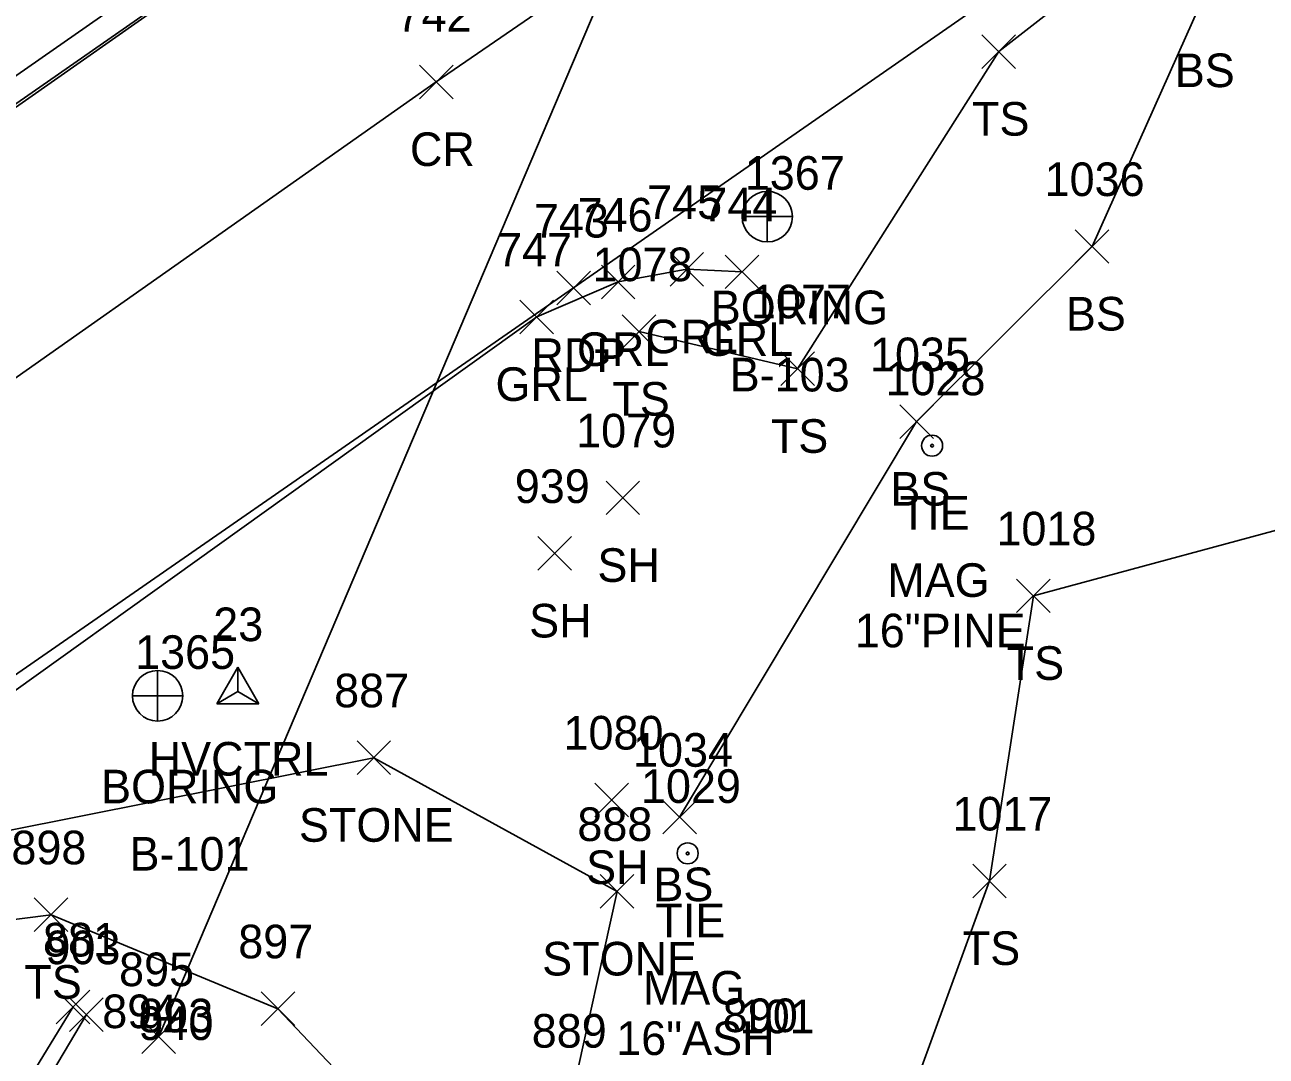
# Model space of a CAD drawing. Extents: x 1528286 to 1556263, y 492387 to 508952.
# Drawn here: x 1528636.2 to 1528710.1, y 492732.7 to 492794 of the extents above; entities that cross this region are included whole.
import ezdxf

# ---------------------------------------------------------------- set-up
doc = ezdxf.new("R2010")
doc.units = 0
for name, color, linetype in [('C_A', 7, 'Continuous'), ('C_C', 7, 'Continuous'), ('C_I', 7, 'Continuous'), ('CBP', 7, 'Continuous'), ('CPSM', 7, 'Continuous'), ('D_I', 7, 'Continuous'), ('D_TIC', 7, 'Continuous'), ('DCP', 7, 'Continuous'), ('G_A', 7, 'Continuous'), ('G_C', 7, 'Continuous'), ('G_I', 7, 'Continuous'), ('GA_P', 7, 'Continuous'), ('L_A', 7, 'Continuous'), ('L_I', 7, 'Continuous'), ('L_TIC', 7, 'Continuous'), ('LASF', 7, 'Continuous'), ('LAWE', 7, 'Continuous'), ('LELB', 7, 'Continuous'), ('M_I', 7, 'Continuous'), ('P_A', 7, 'Continuous'), ('P_I', 7, 'Continuous'), ('P_TIC', 7, 'Continuous'), ('PET', 7, 'Continuous'), ('PRC', 7, 'Continuous'), ('R_A', 7, 'Continuous'), ('R_I', 7, 'Continuous'), ('R_TIC', 7, 'Continuous'), ('RGR', 7, 'Continuous')]:
    doc.layers.add(name, color=color, linetype=linetype)

msp = doc.modelspace()

# ---------------------------------------------------------------- linework, layer by layer
at = {"layer": 'CBP'}
for centre, radius in [((1528690.22, 492769.002), 0.625), ((1528690.22, 492769.002), 0.625), ((1528690.22, 492769.002), 0.0833), ((1528690.22, 492769.002), 0.0833), ((1528675.675, 492744.745), 0.625), ((1528675.675, 492744.745), 0.625), ((1528675.675, 492744.745), 0.0833), ((1528675.675, 492744.745), 0.0833)]:
    msp.add_circle(centre, radius, dxfattribs=at)
at = {"layer": 'CPSM'}
for p, q in [((1528647.655, 492753.65), (1528648.905, 492755.815)), ((1528647.655, 492753.65), (1528648.905, 492755.815)), ((1528650.155, 492753.65), (1528648.905, 492755.815)), ((1528648.905, 492754.371), (1528648.905, 492755.815)), ((1528650.155, 492753.65), (1528648.905, 492755.815)), ((1528648.905, 492754.371), (1528648.905, 492755.815)), ((1528647.655, 492753.65), (1528648.905, 492754.371)), ((1528647.655, 492753.65), (1528648.905, 492754.371)), ((1528648.905, 492754.371), (1528648.905, 492754.371)), ((1528648.905, 492754.371), (1528650.155, 492753.65)), ((1528648.905, 492754.371), (1528648.905, 492754.371)), ((1528648.905, 492754.371), (1528650.155, 492753.65)), ((1528647.655, 492753.65), (1528650.155, 492753.65)), ((1528647.655, 492753.65), (1528650.155, 492753.65))]:
    msp.add_line(p, q, dxfattribs=at)
at = {"layer": 'D_TIC'}
for points in [[(1528643.198, 492732.843), (1528645.198, 492734.843)], [(1528645.198, 492732.843), (1528643.198, 492734.843)], [(1528643.198, 492732.843), (1528645.198, 492734.843)], [(1528645.198, 492732.843), (1528643.198, 492734.843)]]:
    msp.add_lwpolyline(points, dxfattribs=at)
at = {"layer": 'DCP'}
msp.add_lwpolyline([(1528644.198, 492733.843), (1528697.661, 492859.59)], dxfattribs=at)
msp.add_lwpolyline([(1528644.198, 492733.843), (1528697.661, 492859.59)], dxfattribs=at)
at = {"layer": 'GA_P'}
for p, q in [((1528680.416, 492782.628), (1528680.416, 492784.128)), ((1528680.416, 492782.628), (1528680.416, 492784.128)), ((1528680.416, 492782.628), (1528678.916, 492782.628)), ((1528680.416, 492782.628), (1528678.916, 492782.628)), ((1528681.916, 492782.628), (1528680.416, 492782.628)), ((1528680.416, 492781.128), (1528680.416, 492782.628)), ((1528681.916, 492782.628), (1528680.416, 492782.628)), ((1528680.416, 492781.128), (1528680.416, 492782.628)), ((1528644.13, 492754.118), (1528644.13, 492755.618)), ((1528644.13, 492754.118), (1528644.13, 492755.618)), ((1528644.13, 492754.118), (1528642.63, 492754.118)), ((1528644.13, 492754.118), (1528642.63, 492754.118)), ((1528645.63, 492754.118), (1528644.13, 492754.118)), ((1528644.13, 492752.618), (1528644.13, 492754.118)), ((1528645.63, 492754.118), (1528644.13, 492754.118)), ((1528644.13, 492752.618), (1528644.13, 492754.118))]:
    msp.add_line(p, q, dxfattribs=at)
for centre, start, end in [((1528680.415, 492782.628), 90, 180), ((1528680.415, 492782.628), 90, 180), ((1528680.415, 492782.628), 0, 90), ((1528680.415, 492782.628), 0, 90), ((1528680.415, 492782.628), 180, 270), ((1528680.415, 492782.628), 180, 270), ((1528680.415, 492782.628), 270, 0), ((1528680.415, 492782.628), 270, 0), ((1528644.13, 492754.118), 90, 180), ((1528644.13, 492754.118), 90, 180), ((1528644.13, 492754.118), 0, 90), ((1528644.13, 492754.118), 0, 90), ((1528644.13, 492754.118), 180, 270), ((1528644.13, 492754.118), 180, 270), ((1528644.13, 492754.118), 270, 0), ((1528644.13, 492754.118), 270, 0)]:
    msp.add_arc(centre, 1.5, start, end, dxfattribs=at)
at = {"layer": 'L_TIC'}
for points in [[(1528693.188, 492791.448), (1528695.188, 492793.448)], [(1528695.188, 492791.448), (1528693.188, 492793.448)], [(1528693.188, 492791.448), (1528695.188, 492793.448)], [(1528695.188, 492791.448), (1528693.188, 492793.448)], [(1528698.745, 492779.853), (1528700.745, 492781.853)], [(1528700.745, 492779.853), (1528698.745, 492781.853)], [(1528698.745, 492779.853), (1528700.745, 492781.853)], [(1528700.745, 492779.853), (1528698.745, 492781.853)], [(1528671.784, 492774.788), (1528673.784, 492776.788)], [(1528673.784, 492774.788), (1528671.784, 492776.788)], [(1528671.784, 492774.788), (1528673.784, 492776.788)], [(1528673.784, 492774.788), (1528671.784, 492776.788)], [(1528681.217, 492772.575), (1528683.217, 492774.575)], [(1528683.217, 492772.575), (1528681.217, 492774.575)], [(1528681.217, 492772.575), (1528683.217, 492774.575)], [(1528683.217, 492772.575), (1528681.217, 492774.575)], [(1528688.3, 492769.432), (1528690.3, 492771.432)], [(1528690.3, 492769.432), (1528688.3, 492771.432)], [(1528688.3, 492769.432), (1528690.3, 492771.432)], [(1528690.3, 492769.432), (1528688.3, 492771.432)], [(1528670.817, 492764.897), (1528672.817, 492766.897)], [(1528672.817, 492764.897), (1528670.817, 492766.897)], [(1528670.817, 492764.897), (1528672.817, 492766.897)], [(1528672.817, 492764.897), (1528670.817, 492766.897)], [(1528666.755, 492761.589), (1528668.755, 492763.589)], [(1528668.755, 492761.589), (1528666.755, 492763.589)], [(1528666.755, 492761.589), (1528668.755, 492763.589)], [(1528668.755, 492761.589), (1528666.755, 492763.589)], [(1528695.254, 492759.067), (1528697.254, 492761.067)], [(1528697.254, 492759.067), (1528695.254, 492761.067)], [(1528695.254, 492759.067), (1528697.254, 492761.067)], [(1528697.254, 492759.067), (1528695.254, 492761.067)], [(1528655.998, 492749.434), (1528657.998, 492751.434)], [(1528657.998, 492749.434), (1528655.998, 492751.434)], [(1528655.998, 492749.434), (1528657.998, 492751.434)], [(1528657.998, 492749.434), (1528655.998, 492751.434)], [(1528670.145, 492746.922), (1528672.145, 492748.922)], [(1528672.145, 492746.922), (1528670.145, 492748.922)], [(1528670.145, 492746.922), (1528672.145, 492748.922)], [(1528672.145, 492746.922), (1528670.145, 492748.922)], [(1528674.196, 492745.898), (1528676.196, 492747.898)], [(1528676.196, 492745.898), (1528674.196, 492747.898)], [(1528674.196, 492745.898), (1528676.196, 492747.898)], [(1528676.196, 492745.898), (1528674.196, 492747.898)], [(1528692.638, 492742.104), (1528694.638, 492744.104)], [(1528694.638, 492742.104), (1528692.638, 492744.104)], [(1528692.638, 492742.104), (1528694.638, 492744.104)], [(1528694.638, 492742.104), (1528692.638, 492744.104)], [(1528670.474, 492741.478), (1528672.474, 492743.478)], [(1528672.474, 492741.478), (1528670.474, 492743.478)], [(1528670.474, 492741.478), (1528672.474, 492743.478)], [(1528672.474, 492741.478), (1528670.474, 492743.478)], [(1528636.79, 492740.092), (1528638.79, 492742.092)], [(1528638.79, 492740.092), (1528636.79, 492742.092)], [(1528636.79, 492740.092), (1528638.79, 492742.092)], [(1528638.79, 492740.092), (1528636.79, 492742.092)], [(1528638.098, 492734.608), (1528640.098, 492736.608)], [(1528640.098, 492734.608), (1528638.098, 492736.608)], [(1528638.098, 492734.608), (1528640.098, 492736.608)], [(1528640.098, 492734.608), (1528638.098, 492736.608)], [(1528650.291, 492734.499), (1528652.291, 492736.499)], [(1528652.291, 492734.499), (1528650.291, 492736.499)], [(1528650.291, 492734.499), (1528652.291, 492736.499)], [(1528652.291, 492734.499), (1528650.291, 492736.499)], [(1528638.893, 492734.148), (1528640.893, 492736.148)], [(1528640.893, 492734.148), (1528638.893, 492736.148)], [(1528638.893, 492734.148), (1528640.893, 492736.148)], [(1528640.893, 492734.148), (1528638.893, 492736.148)]]:
    msp.add_lwpolyline(points, dxfattribs=at)
at = {"layer": 'LASF'}
msp.add_lwpolyline([(1528639.098, 492735.608), (1528627.241, 492716.245), (1528613.209, 492719.227), (1528607.642, 492721.098), (1528613.116, 492733.507), (1528630.781, 492745.216), (1528656.998, 492750.434), (1528671.474, 492742.478), (1528668.765, 492730.184), (1528658.721, 492713.827), (1528653.721, 492719.292), (1528645.341, 492731.093)], dxfattribs=at)
msp.add_lwpolyline([(1528639.098, 492735.608), (1528627.241, 492716.245), (1528613.209, 492719.227), (1528607.642, 492721.098), (1528613.116, 492733.507), (1528630.781, 492745.216), (1528656.998, 492750.434), (1528671.474, 492742.478), (1528668.765, 492730.184), (1528658.721, 492713.827), (1528653.721, 492719.292), (1528645.341, 492731.093)], dxfattribs=at)
at = {"layer": 'LAWE'}
msp.add_lwpolyline([(1528639.893, 492735.148), (1528628.638, 492716.197), (1528619.322, 492697.772), (1528600.014, 492685.78), (1528586.494, 492675.208), (1528555.765, 492651.711), (1528552.059, 492644.142), (1528537.626, 492632.534), (1528523.345, 492621.851), (1528510.87, 492609.533), (1528497.291, 492599.489), (1528482.777, 492583.151), (1528460.774, 492562.048), (1528436.992, 492551.704), (1528418.951, 492545.204), (1528399.482, 492529.93), (1528387.952, 492519.312), (1528358.196, 492480.955)], dxfattribs=at)
msp.add_lwpolyline([(1528639.893, 492735.148), (1528628.638, 492716.197), (1528619.322, 492697.772), (1528600.014, 492685.78), (1528586.494, 492675.208), (1528555.765, 492651.711), (1528552.059, 492644.142), (1528537.626, 492632.534), (1528523.345, 492621.851), (1528510.87, 492609.533), (1528497.291, 492599.489), (1528482.777, 492583.151), (1528460.774, 492562.048), (1528436.992, 492551.704), (1528418.951, 492545.204), (1528399.482, 492529.93), (1528387.952, 492519.312), (1528358.196, 492480.955)], dxfattribs=at)
at = {"layer": 'LELB'}
for points in [[(1528511.531, 492702.846), (1528534.14, 492721.314), (1528572.642, 492751.164), (1528586.729, 492763.586), (1528600.497, 492766.346), (1528613.458, 492775.516), (1528652.2, 492802.526), (1528688.619, 492828.262), (1528710.289, 492843.118), (1528742.907, 492866.471), (1528778.713, 492891.266), (1528817.445, 492919.082), (1528857.746, 492946.937), (1528897.372, 492973.983), (1528940.286, 493003.739)], [(1528511.531, 492702.846), (1528534.14, 492721.314), (1528572.642, 492751.164), (1528586.729, 492763.586), (1528600.497, 492766.346), (1528613.458, 492775.516), (1528652.2, 492802.526), (1528688.619, 492828.262), (1528710.289, 492843.118), (1528742.907, 492866.471), (1528778.713, 492891.266), (1528817.445, 492919.082), (1528857.746, 492946.937), (1528897.372, 492973.983), (1528940.286, 493003.739)], [(1528946.969, 492932.586), (1528919.959, 492926.163), (1528896.398, 492920.638), (1528892.931, 492919.077), (1528869.957, 492910.976), (1528843.058, 492896.384), (1528834.233, 492890.275), (1528806.992, 492871.856), (1528782.492, 492854.983), (1528750.989, 492833.046), (1528710.78, 492805.361), (1528694.188, 492792.448), (1528682.217, 492773.575), (1528672.784, 492775.788)], [(1528946.969, 492932.586), (1528919.959, 492926.163), (1528896.398, 492920.638), (1528892.931, 492919.077), (1528869.957, 492910.976), (1528843.058, 492896.384), (1528834.233, 492890.275), (1528806.992, 492871.856), (1528782.492, 492854.983), (1528750.989, 492833.046), (1528710.78, 492805.361), (1528694.188, 492792.448), (1528682.217, 492773.575), (1528672.784, 492775.788)], [(1528675.196, 492746.898), (1528689.3, 492770.432), (1528699.745, 492780.853), (1528706.225, 492795.334), (1528738.423, 492819.149), (1528757.61, 492832.596), (1528783.379, 492849.877), (1528832.015, 492885.927)], [(1528675.196, 492746.898), (1528689.3, 492770.432), (1528699.745, 492780.853), (1528706.225, 492795.334), (1528738.423, 492819.149), (1528757.61, 492832.596), (1528783.379, 492849.877), (1528832.015, 492885.927)], [(1528705.259, 492704.943), (1528686.116, 492722.486), (1528693.638, 492743.104), (1528696.254, 492760.067), (1528714.163, 492764.9), (1528717.514, 492785.825)], [(1528705.259, 492704.943), (1528686.116, 492722.486), (1528693.638, 492743.104), (1528696.254, 492760.067), (1528714.163, 492764.9), (1528717.514, 492785.825)], [(1528661.587, 492724.641), (1528651.291, 492735.499), (1528637.79, 492741.092), (1528626.005, 492739.602), (1528615.037, 492725.446), (1528613.03, 492719.826)], [(1528661.587, 492724.641), (1528651.291, 492735.499), (1528637.79, 492741.092), (1528626.005, 492739.602), (1528615.037, 492725.446), (1528613.03, 492719.826)]]:
    msp.add_lwpolyline(points, dxfattribs=at)
at = {"layer": 'P_TIC'}
for points in [[(1528659.714, 492789.64), (1528661.714, 492791.64)], [(1528661.714, 492789.64), (1528659.714, 492791.64)], [(1528659.714, 492789.64), (1528661.714, 492791.64)], [(1528661.714, 492789.64), (1528659.714, 492791.64)], [(1528667.887, 492777.385), (1528669.887, 492779.385)], [(1528669.887, 492777.385), (1528667.887, 492779.385)], [(1528667.887, 492777.385), (1528669.887, 492779.385)], [(1528669.887, 492777.385), (1528667.887, 492779.385)]]:
    msp.add_lwpolyline(points, dxfattribs=at)
at = {"layer": 'PET'}
for points in [[(1528796.008, 492866.532), (1528760.738, 492842.185), (1528727.561, 492819.312), (1528705.978, 492804.168), (1528668.887, 492778.385)], [(1528796.008, 492866.532), (1528760.738, 492842.185), (1528727.561, 492819.312), (1528705.978, 492804.168), (1528668.887, 492778.385)], [(1528653.332, 492801.515), (1528614.2, 492774.085)], [(1528653.332, 492801.515), (1528614.2, 492774.085)], [(1528668.887, 492778.385), (1528630.871, 492752.063)], [(1528668.887, 492778.385), (1528630.871, 492752.063)]]:
    msp.add_lwpolyline(points, dxfattribs=at)
at = {"layer": 'PRC'}
for points in [[(1528788.693, 492878.598), (1528752.937, 492854.076), (1528719.055, 492830.747), (1528697.879, 492816.158), (1528660.714, 492790.64)], [(1528788.693, 492878.598), (1528752.937, 492854.076), (1528719.055, 492830.747), (1528697.879, 492816.158), (1528660.714, 492790.64)], [(1528660.714, 492790.64), (1528622.148, 492763.521)], [(1528660.714, 492790.64), (1528622.148, 492763.521)]]:
    msp.add_lwpolyline(points, dxfattribs=at)
at = {"layer": 'R_TIC'}
for points in [[(1528674.624, 492778.498), (1528676.624, 492780.498)], [(1528676.624, 492778.498), (1528674.624, 492780.498)], [(1528674.624, 492778.498), (1528676.624, 492780.498)], [(1528676.624, 492778.498), (1528674.624, 492780.498)], [(1528677.913, 492778.345), (1528679.913, 492780.345)], [(1528679.913, 492778.345), (1528677.913, 492780.345)], [(1528677.913, 492778.345), (1528679.913, 492780.345)], [(1528679.913, 492778.345), (1528677.913, 492780.345)], [(1528670.539, 492777.742), (1528672.539, 492779.742)], [(1528672.539, 492777.742), (1528670.539, 492779.742)], [(1528670.539, 492777.742), (1528672.539, 492779.742)], [(1528672.539, 492777.742), (1528670.539, 492779.742)], [(1528665.696, 492775.663), (1528667.696, 492777.663)], [(1528667.696, 492775.663), (1528665.696, 492777.663)], [(1528665.696, 492775.663), (1528667.696, 492777.663)], [(1528667.696, 492775.663), (1528665.696, 492777.663)]]:
    msp.add_lwpolyline(points, dxfattribs=at)
at = {"layer": 'RGR'}
for points in [[(1528653.301, 492801.623), (1528614.133, 492774.352)], [(1528653.301, 492801.623), (1528614.133, 492774.352)], [(1528678.913, 492779.345), (1528675.624, 492779.498), (1528671.539, 492778.742), (1528666.696, 492776.663)], [(1528678.913, 492779.345), (1528675.624, 492779.498), (1528671.539, 492778.742), (1528666.696, 492776.663)], [(1528666.696, 492776.663), (1528631.557, 492751.518)], [(1528666.696, 492776.663), (1528631.557, 492751.518)]]:
    msp.add_lwpolyline(points, dxfattribs=at)

# ---------------------------------------------------------------- texts
at = {"layer": 'C_A'}
for s, p in [('TIE', (1528688.299, 492764.002)), ('TIE', (1528688.299, 492764.002)), ('HVCTRL', (1528643.598, 492749.371)), ('HVCTRL', (1528643.598, 492749.371)), ('TIE', (1528673.754, 492739.745)), ('TIE', (1528673.754, 492739.745))]:
    msp.add_text(s, height=2, dxfattribs=at).set_placement(p)
at = {"layer": 'C_C'}
for s, p in [('MAG', (1528687.551, 492760.002)), ('MAG', (1528687.551, 492760.002)), ('16"PINE', (1528685.622, 492757.002)), ('16"PINE', (1528685.622, 492757.002)), ('MAG', (1528673.006, 492735.745)), ('MAG', (1528673.006, 492735.745)), ('16"ASH', (1528671.423, 492732.745)), ('16"ASH', (1528671.423, 492732.745))]:
    msp.add_text(s, height=2, dxfattribs=at).set_placement(p)
at = {"layer": 'C_I'}
for s, p in [('1028', (1528687.449, 492772.002)), ('1028', (1528687.449, 492772.002)), ('23', (1528647.44, 492757.371)), ('23', (1528647.44, 492757.371)), ('1029', (1528672.896, 492747.745)), ('1029', (1528672.896, 492747.745)), ('890', (1528677.766, 492734.109)), ('890', (1528677.766, 492734.109))]:
    msp.add_text(s, height=2, dxfattribs=at).set_placement(p)
at = {"layer": 'D_I'}
msp.add_text('895', height=2, dxfattribs=at).set_placement((1528641.835, 492736.843))
msp.add_text('895', height=2, dxfattribs=at).set_placement((1528641.835, 492736.843))
at = {"layer": 'G_A'}
for p in [(1528677.052, 492776.228), (1528677.052, 492776.228), (1528640.766, 492747.718), (1528640.766, 492747.718)]:
    msp.add_text('BORING', height=2, dxfattribs=at).set_placement(p)
at = {"layer": 'G_C'}
for s, p in [('B-103', (1528678.178, 492772.228)), ('B-103', (1528678.178, 492772.228)), ('B-101', (1528642.459, 492743.718)), ('B-101', (1528642.459, 492743.718))]:
    msp.add_text(s, height=2, dxfattribs=at).set_placement(p)
at = {"layer": 'G_I'}
for s, p in [('1367', (1528679.075, 492784.228)), ('1367', (1528679.075, 492784.228)), ('1365', (1528642.79, 492755.718)), ('1365', (1528642.79, 492755.718))]:
    msp.add_text(s, height=2, dxfattribs=at).set_placement(p)
at = {"layer": 'L_A'}
for s, p in [('BS', (1528704.666, 492790.334)), ('BS', (1528704.666, 492790.334)), ('TS', (1528692.598, 492787.448)), ('TS', (1528692.598, 492787.448)), ('BS', (1528698.186, 492775.853)), ('BS', (1528698.186, 492775.853)), ('TS', (1528671.194, 492770.788)), ('TS', (1528671.194, 492770.788)), ('TS', (1528680.626, 492768.575)), ('TS', (1528680.626, 492768.575)), ('BS', (1528687.741, 492765.432)), ('BS', (1528687.741, 492765.432)), ('SH', (1528670.305, 492760.897)), ('SH', (1528670.305, 492760.897)), ('SH', (1528666.243, 492757.589)), ('SH', (1528666.243, 492757.589)), ('TS', (1528694.664, 492755.067)), ('TS', (1528694.664, 492755.067)), ('STONE', (1528652.541, 492745.434)), ('STONE', (1528652.541, 492745.434)), ('SH', (1528669.633, 492742.922)), ('SH', (1528669.633, 492742.922)), ('BS', (1528673.636, 492741.898)), ('BS', (1528673.636, 492741.898)), ('TS', (1528692.048, 492738.104)), ('TS', (1528692.048, 492738.104)), ('STONE', (1528667.017, 492737.478)), ('STONE', (1528667.017, 492737.478)), ('TS', (1528636.199, 492736.092)), ('TS', (1528636.199, 492736.092))]:
    msp.add_text(s, height=2, dxfattribs=at).set_placement(p)
at = {"layer": 'L_I'}
for s, p in [('1036', (1528696.919, 492783.853)), ('1036', (1528696.919, 492783.853)), ('1078', (1528670.013, 492778.788)), ('1078', (1528670.013, 492778.788)), ('1077', (1528679.445, 492776.575)), ('1077', (1528679.445, 492776.575)), ('1035', (1528686.528, 492773.432)), ('1035', (1528686.528, 492773.432)), ('1079', (1528669.038, 492768.897)), ('1079', (1528669.038, 492768.897)), ('939', (1528665.385, 492765.589)), ('939', (1528665.385, 492765.589)), ('1018', (1528694.05, 492763.067)), ('1018', (1528694.05, 492763.067)), ('887', (1528654.636, 492753.434)), ('887', (1528654.636, 492753.434)), ('1080', (1528668.286, 492750.922)), ('1080', (1528668.286, 492750.922)), ('1034', (1528672.424, 492749.898)), ('1034', (1528672.424, 492749.898)), ('1017', (1528691.434, 492746.104)), ('1017', (1528691.434, 492746.104)), ('888', (1528669.111, 492745.478)), ('888', (1528669.111, 492745.478)), ('898', (1528635.428, 492744.092)), ('898', (1528635.428, 492744.092)), ('881', (1528637.303, 492738.608)), ('881', (1528637.303, 492738.608)), ('903', (1528637.452, 492738.148)), ('903', (1528637.452, 492738.148)), ('897', (1528648.929, 492738.499)), ('897', (1528648.929, 492738.499)), ('894', (1528640.836, 492734.345)), ('894', (1528640.836, 492734.345)), ('893', (1528642.979, 492734.093)), ('893', (1528642.979, 492734.093)), ('940', (1528642.989, 492733.638)), ('940', (1528642.989, 492733.638)), ('889', (1528666.395, 492733.184)), ('889', (1528666.395, 492733.184))]:
    msp.add_text(s, height=2, dxfattribs=at).set_placement(p)
at = {"layer": 'M_I'}
msp.add_text('101', height=2, dxfattribs=at).set_placement((1528678.771, 492734.038))
msp.add_text('101', height=2, dxfattribs=at).set_placement((1528678.771, 492734.038))
at = {"layer": 'P_A'}
for s, p in [('CR', (1528659.147, 492785.64)), ('CR', (1528659.147, 492785.64)), ('RDP', (1528666.375, 492773.385)), ('RDP', (1528666.375, 492773.385))]:
    msp.add_text(s, height=2, dxfattribs=at).set_placement(p)
at = {"layer": 'P_I'}
for s, p in [('742', (1528658.351, 492793.64)), ('742', (1528658.351, 492793.64)), ('743', (1528666.525, 492781.385)), ('743', (1528666.525, 492781.385))]:
    msp.add_text(s, height=2, dxfattribs=at).set_placement(p)
at = {"layer": 'R_A'}
for p in [(1528673.168, 492774.498), (1528673.168, 492774.498), (1528676.456, 492774.345), (1528676.456, 492774.345), (1528669.083, 492773.742), (1528669.083, 492773.742), (1528664.239, 492771.663), (1528664.239, 492771.663)]:
    msp.add_text('GRL', height=2, dxfattribs=at).set_placement(p)
at = {"layer": 'R_I'}
for s, p in [('745', (1528673.262, 492782.498)), ('745', (1528673.262, 492782.498)), ('744', (1528676.55, 492782.345)), ('744', (1528676.55, 492782.345)), ('746', (1528669.122, 492781.742)), ('746', (1528669.122, 492781.742)), ('747', (1528664.334, 492779.663)), ('747', (1528664.334, 492779.663))]:
    msp.add_text(s, height=2, dxfattribs=at).set_placement(p)

doc.saveas('drawing.dxf')
